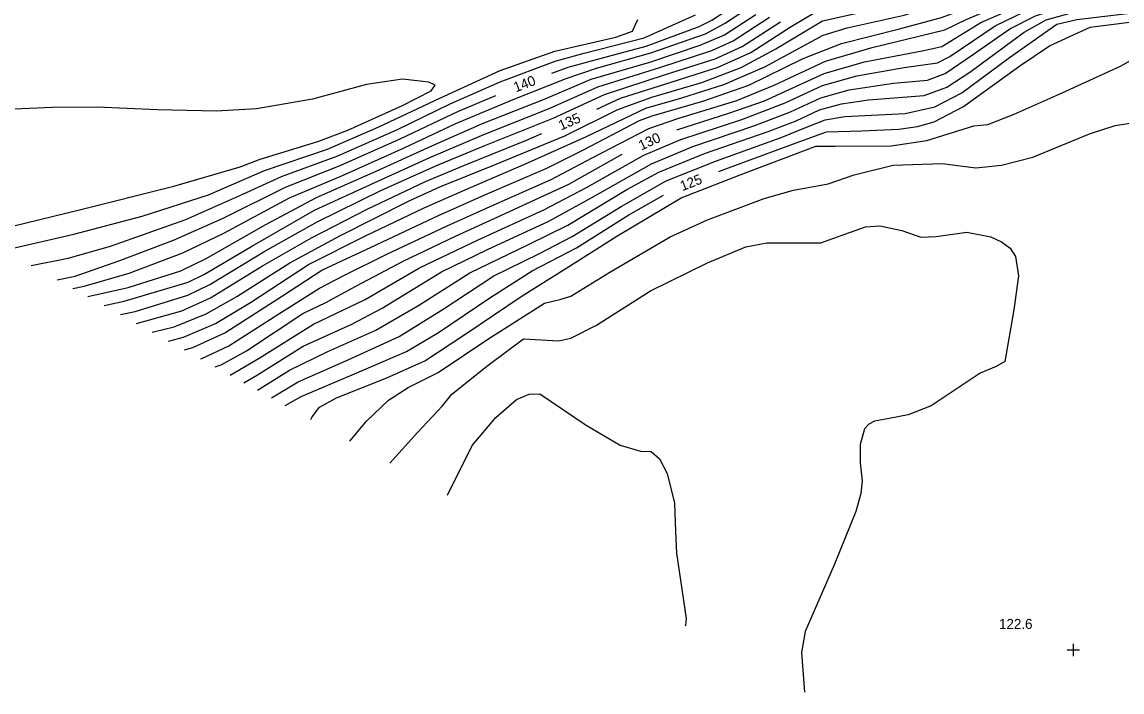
# Model space of a CAD drawing. Extents: x 1475150 to 2003689, y 770235 to 1112803.
# Drawn here: x 2001916.8 to 2002136.4, y 770717 to 770850.8 of the extents above; entities that cross this region are included whole.
import ezdxf

# ---------------------------------------------------------------- set-up
doc = ezdxf.new("R2010")
doc.units = 0
for name, color, linetype in [('RD_DTM_Major1', 7, 'Continuous'), ('RD_DTM_Major1_Lbl', 7, 'Continuous'), ('RD_DTM_Minor1', 7, 'Continuous'), ('RD_DTM_Spot_Elev', 7, 'Continuous')]:
    doc.layers.add(name, color=color, linetype=linetype)

msp = doc.modelspace()

# ---------------------------------------------------------------- linework, layer by layer
at = {"layer": 'RD_DTM_Major1'}
for points in [[(2002022.61, 770840.56), (2002025.86, 770841.81), (2002033.01, 770843.7), (2002041.4, 770845.99), (2002052.02, 770849.9), (2002054.51, 770851.14), (2002063.17, 770856.97), (2002068.42, 770859.71), (2002077.81, 770864.64), (2002083.41, 770867.25), (2002086.3, 770868.74), (2002094.53, 770875.51), (2002102.86, 770883.77), (2002109.13, 770896.96), (2002114.98, 770907.54), (2002119.84, 770917.39), (2002123.89, 770924.28), (2002130.63, 770934.4), (2002137.21, 770945.15)], [(2002031.57, 770833.39), (2002036.29, 770835.57), (2002046.62, 770838.85), (2002055.83, 770841.77), (2002062.32, 770844.71), (2002070.38, 770849.89), (2002075.28, 770852.8), (2002077.26, 770853.49), (2002088.46, 770856.14), (2002094.49, 770857.99), (2002101.73, 770862.24), (2002113.79, 770867.1), (2002122.86, 770871.88), (2002126.96, 770873.43), (2002137.57, 770876.06), (2002153.2, 770879.35), (2002163.12, 770884.46), (2002164.69, 770885.2)], [(2002047.58, 770829.29), (2002057.94, 770832.56), (2002065.07, 770835.06), (2002076.94, 770840.53), (2002084.99, 770842.87), (2002096.84, 770845.09), (2002100.48, 770845.91), (2002108.22, 770850.69), (2002118.55, 770855.17), (2002124.92, 770857.23), (2002137.21, 770860.57), (2002149.77, 770864.44), (2002163.78, 770867.39), (2002172.56, 770873.71), (2002181.06, 770877.45), (2002183.7, 770878.47)], [(2002055.94, 770820.93), (2002057.84, 770821.68), (2002072.12, 770826.93), (2002077.4, 770828.83), (2002084.48, 770829.09), (2002091.88, 770829.38), (2002095.56, 770829.93), (2002098.89, 770830.89), (2002104.79, 770833.9), (2002116.03, 770842.06), (2002121.96, 770846.02), (2002130.09, 770849.75), (2002137.91, 770850.78)], [(2001923.88, 770799.32), (2001927.44, 770800.03), (2001936.38, 770803.18), (2001947.07, 770807.24), (2001957, 770811.59), (2001969.45, 770817.83), (2001980.34, 770822.12), (2001992.45, 770827.5), (2002003.98, 770833.02), (2002011.45, 770836.13)], [(2001939.67, 770790.6), (2001948.71, 770793.13), (2001954.48, 770795.7), (2001964.83, 770802.08), (2001974.63, 770807.68), (2001985.71, 770813.42), (2001997.41, 770818.95), (2002005.04, 770822.11), (2002017.56, 770827.2), (2002020.6, 770828.52)], [(2001955.38, 770781.93), (2001956.56, 770782.29), (2001961.65, 770785.13), (2001972.86, 770792.59), (2001977.45, 770794.8), (2001983.63, 770798.07), (2001992.95, 770803.04), (2002003.37, 770808.04), (2002012.58, 770812.23), (2002025.99, 770818.44), (2002036.62, 770824.39)], [(2001969.39, 770774.19), (2001972.57, 770775.99), (2001983.23, 770780.55), (2001993.6, 770785.01), (2001999.95, 770788.81), (2002010.2, 770795.72), (2002018.7, 770801.08), (2002027.49, 770805.69), (2002037.98, 770812.26), (2002044.89, 770816.23)]]:
    msp.add_lwpolyline(points, dxfattribs=at)
at = {"layer": 'RD_DTM_Minor1'}
for points in [[(2001942.84, 770788.85), (2001947.2, 770789.93), (2001953.61, 770792.48), (2001959.73, 770795.98), (2001970.29, 770802.72), (2001980.3, 770808.12), (2001994.11, 770815.11), (2002000.26, 770817.87), (2002011.15, 770822.3), (2002025.22, 770828.07), (2002035.75, 770833.32), (2002042.56, 770835.77), (2002052.54, 770838.74), (2002060.4, 770841.71), (2002067.31, 770845.44), (2002076.65, 770851), (2002089.28, 770853.84), (2002096.65, 770856.06), (2002100.31, 770858.24), (2002109.33, 770861.56), (2002118.82, 770865.26), (2002124.98, 770867.99), (2002137.88, 770871.18)], [(2001946.05, 770787.08), (2001949.08, 770787.85), (2001955.46, 770790.6), (2001962.45, 770794.8), (2001974.01, 770802.33), (2001985.38, 770808.11), (2001997.14, 770813.7), (2002005.9, 770817.57), (2002017.35, 770822.45), (2002029.49, 770827.95), (2002041.36, 770833.57), (2002048.57, 770835.64), (2002056.94, 770838.3), (2002065.09, 770841.86), (2002076.77, 770848.16), (2002081.57, 770849.62), (2002092.93, 770852.16), (2002098.31, 770853.87), (2002099.52, 770854.57), (2002107, 770857.31), (2002120.97, 770861.87), (2002128.28, 770864.49), (2002137.8, 770868.09)], [(2001949.24, 770785.32), (2001950.96, 770785.77), (2001957.32, 770788.72), (2001968.84, 770796.12), (2001976.7, 770801.21), (2001986.53, 770805.83), (2002000, 770812.18), (2002009.21, 770816.25), (2002021.6, 770821.62), (2002028.95, 770825.25), (2002040.08, 770831.13), (2002042.64, 770832.08), (2002052.74, 770834.97), (2002061.94, 770838.19), (2002072.77, 770843.53), (2002080.41, 770846.53), (2002091.99, 770849.46), (2002100.36, 770851.73), (2002109.11, 770854.88), (2002120.91, 770859.63), (2002129.42, 770862.52), (2002143.69, 770867.7)], [(2001952.47, 770783.53), (2001952.71, 770783.6), (2001958.13, 770786.12), (2001968.09, 770792.5), (2001976.23, 770797.61), (2001981.08, 770800.18), (2001989.69, 770804.41), (2002001.68, 770810.11), (2002010.89, 770814.24), (2002022.44, 770819.34), (2002030.68, 770823.67), (2002041.98, 770829.53), (2002047.95, 770831.59), (2002059.53, 770835.13), (2002066.97, 770838.2), (2002077.26, 770842.96), (2002086.51, 770845.68), (2002101.03, 770849.21), (2002105.32, 770851.33), (2002116.9, 770856.23), (2002125.94, 770859.32), (2002135.4, 770862.32), (2002149.03, 770866.81)], [(2001958.41, 770780.25), (2001964.19, 770783.67), (2001975.04, 770790.42), (2001985.32, 770795.35), (2001996.2, 770801.67), (2002007.89, 770807.32), (2002020.99, 770813.27), (2002029.49, 770817.75), (2002040.97, 770824.18), (2002048.35, 770827.36), (2002060.54, 770831.35), (2002069.16, 770834.64), (2002076.63, 770838.09), (2002083.47, 770840.06), (2002092.94, 770841.71), (2002099.58, 770842.64), (2002102.02, 770843.94), (2002111.11, 770850.05), (2002117.01, 770852.87), (2002123.34, 770855.11), (2002135.48, 770857.79), (2002146.66, 770861.16)], [(2001926.98, 770797.6), (2001929.27, 770798.06), (2001938.22, 770800.63), (2001948.91, 770804.67), (2001957.15, 770808.62), (2001970.25, 770815.7), (2001980.79, 770820.16), (2001993.13, 770825.65), (2002003.45, 770830.53), (2002014.88, 770835.3), (2002025.46, 770839.54), (2002031.48, 770841.56), (2002042.37, 770844.62), (2002053.29, 770848.45), (2002057.09, 770850.48), (2002066.22, 770856.54)], [(2001961.14, 770778.75), (2001963.85, 770780.35), (2001972.98, 770786.07), (2001982.64, 770790.42), (2001988.74, 770793.65), (2002000.54, 770800.87), (2002009.73, 770805.34), (2002022.01, 770811.02), (2002030.71, 770815.81), (2002042.46, 770822.49), (2002050.72, 770825.94), (2002063.14, 770830.14), (2002070.25, 770832.85), (2002076.32, 770835.66), (2002081.96, 770837.25), (2002090.82, 770838.56), (2002097.61, 770839.18), (2002101.11, 770840.48), (2002106.77, 770844.36), (2002114.01, 770849.41), (2002119.15, 770852.04), (2002124.7, 770853.83), (2002137.5, 770856.21)], [(2001963.85, 770777.25), (2001970.2, 770781.25), (2001977.9, 770785), (2001987.44, 770789.23), (2001996.2, 770794.33), (2002006.23, 770800.69), (2002017.94, 770806.35), (2002025.81, 770810.24), (2002037.59, 770817.35), (2002043.95, 770820.79), (2002053.1, 770824.52), (2002065.75, 770828.93), (2002071.34, 770831.07), (2002076, 770833.23), (2002080.44, 770834.45), (2002085.83, 770835.23), (2002096.92, 770836.1), (2002101.42, 770837.77), (2002106.01, 770840.76), (2002116.9, 770848.77), (2002121.29, 770851.21), (2002126.07, 770852.56), (2002139.52, 770854.63)], [(2001918.68, 770802.19), (2001926.04, 770803.61), (2001934.47, 770806.03), (2001949.53, 770811.38), (2001960.93, 770816.42), (2001968.65, 770819.96), (2001979.9, 770824.07), (2001991.77, 770829.35), (2002002.31, 770834.44), (2002012.29, 770838.84), (2002023.24, 770842.96), (2002029.08, 770844.56), (2002041.03, 770847.63), (2002051.29, 770852.24)], [(2001930, 770795.94), (2001938.04, 770797.8), (2001948.54, 770801.08), (2001953.59, 770803.59), (2001965.5, 770810.37), (2001975.61, 770815.73), (2001987.53, 770820.99), (2001998.63, 770826.09), (2002008.76, 770830.51), (2002021.28, 770835.48), (2002030.46, 770839.38), (2002042.16, 770842.76), (2002052.19, 770846.18), (2002057.06, 770848.21), (2002063.3, 770852.32)], [(2001933.24, 770794.15), (2001937.23, 770795.03), (2001950.03, 770798.82), (2001953.27, 770800.46), (2001962.83, 770806.12), (2001975.25, 770813.21), (2001987.15, 770818.68), (2001998.22, 770823.71), (2002008.99, 770828.31), (2002022.07, 770833.53), (2002031.79, 770837.87), (2002044.36, 770841.8), (2002054.56, 770845.11), (2002058.82, 770847.04), (2002066.03, 770851.77)], [(2001966.62, 770775.72), (2001971.97, 770778.9), (2001982.07, 770783.4), (2001992.11, 770787.97), (2002000.91, 770793.44), (2002011.05, 770800.07), (2002020, 770804.52), (2002026.65, 770807.97), (2002036.45, 770813.98), (2002045.44, 770819.1), (2002055.47, 770823.1), (2002068.35, 770827.73), (2002073.45, 770829.8), (2002077.14, 770831.25), (2002081.06, 770831.95), (2002093.11, 770832.55), (2002099.07, 770833.84), (2002104.43, 770836.68), (2002113.96, 770843.7), (2002123.42, 770850.38), (2002127.43, 770851.29), (2002138.04, 770852.54)], [(2001913.63, 770805.3), (2001927.17, 770808.45), (2001940.81, 770812.02), (2001954.04, 770816.26), (2001965.26, 770821.16), (2001977.8, 770825.39), (2001988.09, 770829.83), (2002000.26, 770835.61), (2002012.31, 770841.14), (2002023.17, 770844.96), (2002035.35, 770847.76), (2002038.73, 770848.98), (2002039.29, 770850.27), (2002039.76, 770851.28)], [(2001936.5, 770792.35), (2001939.41, 770793), (2001949.9, 770796.23), (2001954.31, 770798.34), (2001965.33, 770805), (2001975.77, 770810.88), (2001988.48, 770817.11), (2001999.43, 770822.04), (2002009.21, 770826.1), (2002022.85, 770831.58), (2002033.11, 770836.35), (2002045.3, 770840.3), (2002055.19, 770843.44), (2002060.57, 770845.88), (2002068.23, 770850.85)], [(2001974.47, 770771.39), (2001974.72, 770771.93), (2001976.24, 770773.88), (2001979.6, 770775.72), (2001989.67, 770779.73), (2001997.24, 770783.13), (2002005.43, 770788.49), (2002016.45, 770795.97), (2002026.1, 770802.03), (2002035.6, 770808.03), (2002048.42, 770815.71), (2002060.22, 770820.26), (2002075.31, 770825.98), (2002079.18, 770826), (2002090.36, 770826.04), (2002097.44, 770827.15), (2002106.86, 770830.08), (2002109.62, 770830.32), (2002114.92, 770832.38), (2002124.44, 770836.67), (2002136.25, 770842.03), (2002142.15, 770845.43)], [(2001909.39, 770808.71), (2001928.3, 770813.29), (2001947.15, 770818), (2001960.36, 770821.87), (2001964.37, 770823.38), (2001975.9, 770826.95), (2001981.86, 770829.2), (2001992.77, 770834.11), (2001998.52, 770837.08), (2001999.32, 770838.21), (2001998.04, 770838.81), (2001992.78, 770839.39), (2001985.59, 770838.29), (2001974.82, 770835.36), (2001963.61, 770833.44), (2001955.57, 770832.98), (2001943.91, 770833.23), (2001931.79, 770833.82), (2001922.88, 770833.72), (2001912.18, 770833.26)], [(2001982.28, 770767.08), (2001985.61, 770771.05), (2001990, 770775.25), (2001993.9, 770777.78), (2001999.89, 770780.78), (2002009.82, 770787.46), (2002021.11, 770794.65), (2002024.49, 770795.46), (2002026.39, 770796.06), (2002034.18, 770800.85), (2002046.25, 770807.91), (2002053.66, 770811.28), (2002064.99, 770815.55), (2002070.85, 770817.22), (2002077.74, 770818.49), (2002082.92, 770820.3), (2002090.76, 770822.22), (2002100.53, 770822.54), (2002107.22, 770821.69), (2002112.36, 770822.19), (2002118.62, 770823.81), (2002129.9, 770828.48), (2002135.02, 770830.1), (2002140.55, 770830.96)], [(2001990.28, 770762.66), (2001995.79, 770768.83), (2002000.8, 770774.13), (2002002.66, 770776.49), (2002009.87, 770782.26), (2002016.94, 770787.54), (2002024.01, 770787.09), (2002026.39, 770787.66), (2002031.53, 770790.24), (2002042.31, 770797.12), (2002053.67, 770802.71), (2002061.32, 770805.92), (2002065.49, 770806.71), (2002076.32, 770806.69), (2002081.07, 770808.44), (2002085.21, 770809.91), (2002088.09, 770810.11), (2002092.47, 770809.15), (2002096.29, 770807.84), (2002099.34, 770807.96), (2002105.46, 770808.81), (2002110.25, 770807.92), (2002112.38, 770806.92), (2002114.06, 770805.6), (2002115.13, 770803.98), (2002115.75, 770800.07), (2002114.83, 770793.33), (2002113.05, 770782.96), (2002111.29, 770781.97), (2002108.09, 770780.63), (2002098.33, 770774.15), (2002093.76, 770772.32), (2002089.96, 770771.61), (2002087.01, 770771.05), (2002085.89, 770770.48), (2002085.03, 770769.54), (2002084.12, 770766.41), (2002084.14, 770762.74), (2002084.56, 770759.17), (2002084.29, 770756.65), (2002083.31, 770753.05), (2002079.03, 770742.51), (2002073.17, 770729.07), (2002072.44, 770724.87), (2002073.05, 770716.97)], [(2002001.77, 770756.32), (2002006.72, 770766.19), (2002011.41, 770771.83), (2002015.52, 770775.42), (2002018.08, 770776.46), (2002020.22, 770776.55), (2002029.43, 770770.28), (2002036.26, 770766.26), (2002040.31, 770765.11), (2002042.43, 770765.01), (2002044.12, 770763.56), (2002045.59, 770760.64), (2002047.08, 770754.7), (2002047.31, 770749.06), (2002047.45, 770744.7), (2002049.41, 770731.65), (2002049.31, 770730.33), (2002049.2, 770730.13)]]:
    msp.add_lwpolyline(points, dxfattribs=at)
at = {"layer": 'RD_DTM_Spot_Elev'}
for p, q in [((2002126.71, 770724.12), (2002126.71, 770726.62)), ((2002125.46, 770725.37), (2002127.96, 770725.37))]:
    msp.add_line(p, q, dxfattribs=at)

# ---------------------------------------------------------------- texts
at = {"layer": 'RD_DTM_Major1_Lbl'}
for s, rotation, p in [('140', 20.9694, (2002015.4, 770836.73)), ('135', 23.5231, (2002024.45, 770829.11)), ('130', 24.9402, (2002040.47, 770825.11)), ('125', 21.3741, (2002048.65, 770817))]:
    msp.add_text(s, height=2, rotation=rotation, dxfattribs=at).set_placement(p)
at = {"layer": 'RD_DTM_Spot_Elev'}
msp.add_text('122.6', height=2, dxfattribs=at).set_placement((2002111.86, 770729.57))

doc.saveas('drawing.dxf')
